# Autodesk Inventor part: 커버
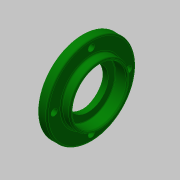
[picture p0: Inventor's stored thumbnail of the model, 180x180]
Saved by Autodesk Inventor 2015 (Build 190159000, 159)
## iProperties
Created: 2018-11
Part Number: 커버
Material: 알루미늄 6061
Document SubType Name: Modeling
Designer: mduedu
Density: 1 g/cm^3
Appearance: 진녹색
Author: mduedu
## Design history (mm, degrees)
sketch "스케치1"
  geometry: L1 (0, 0)-(2, 0); L2 (2, 0)-(2, 20); L3 (2, 20)-(0, 20); L4 (0, 20)-(0, 0); L5 (2, 0)-(8, 0); L6 (8, 0)-(8, 31); L7 (8, 31)-(2, 31); L8 (2, 31)-(2, 0); L9 (8, 0)-(14, 0); L10 (14, 0)-(14, 21); L11 (14, 21)-(8, 21); L12 (8, 21)-(8, 0)
  constraints: 24 end point, 6 parallel, 3 horizontal, 3 perpendicular
  dimensions: "d0" = 62 diameter of L7 L5; "d2" = 42 diameter of L11 L9; "d3" = 40 diameter of L3 L1; "d4" = 2 distance of L2.end L3.end; "d5" = 6 distance of L6.end L7.end; "d6" = 14 distance between parallel lines of L10 L4
revolve "회전1" sketch "스케치1" stored, may be unused: angle "d7" = 90 deg
sketch "스케치2"
  geometry: L1 (0, -20)-(0, 20) reference; L2 (0, 20)-(2, 20) reference; L3 (2, 20)-(2, 31) reference; L4 (2, 31)-(8, 31) reference; L5 (8, 31)-(8, 21) reference; L6 (8, 21)-(14, 21) reference; L7 (14, 21)-(14, -21) reference; L8 (14, -21)-(8, -21) reference; L9 (8, -21)-(8, -31) reference; L10 (8, -31)-(2, -31) reference; L11 (2, -31)-(2, -20) reference; L12 (2, -20)-(0, -20) reference; L13 (0, 0)-(2, 0); L14 (2, 0)-(2, 16.5); L15 (2, 16.5)-(0, 16.5); L16 (0, 16.5)-(0, 0); L17 (2, 0)-(5.7, 0); L18 (5.7, 0)-(5.7, 14); L19 (5.7, 14)-(2, 14); L20 (2, 14)-(2, 0); L21 (5.7, 0)-(14, 0); L22 (14, 0)-(14, 19); L23 (14, 19)-(5.7, 19); L24 (5.7, 19)-(5.7, 0)
  constraints: 24 end point, 6 parallel, 3 horizontal, 3 perpendicular, 1 point on line
  dimensions: "d8" = 38 diameter of L23 L21; "d10" = 28 diameter of L19 L17; "d11" = 33 diameter of L15 L13; "d12" = 2 distance of L14.end L15.end; "d13" = 8.3 distance of L22.end L23.end
revolve "회전2" sketch "스케치2" stored, may be unused: angle "d14" = 90 deg
fillet "모깎기1" dims "d15" = 0.3
chamfer "모따기1" distance "d16" = 0.8; stored, may be unused: second distance "d17" = 2, angle "d18" = 30 deg
fillet "모깎기2" dims "d19" = 1
chamfer "모따기2" distance "d20" = 0.5; stored, may be unused: second distance "d21" = 2, angle "d22" = 30 deg
sketch "스케치3" dims "d23" = 52
  geometry: 6 further points
  constraints: 2 vertical alignment, 1 coincident, 7 other
  dimensions: "d26" = 360 deg dimension on point (0, 0) point (0, 26) (derived)
sketch "스케치4"
  geometry: 4 further points
  constraints: 4 other
hole "구멍1" sketch "스케치4" at (-26, 0), (0, -26), (26, 0), (0, 26) diameter "d28" = 4.5; stored, may be unused: countersink angle "d32" = 90 deg, drill point angle "d34" = 0 deg; dims "d29" = 6, "d30" = 8, "d31" = 4.6, "d33" = 8
node "솔리드1"
node "절단 모서리 투영1"
